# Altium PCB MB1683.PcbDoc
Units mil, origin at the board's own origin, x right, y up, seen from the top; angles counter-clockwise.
Board outline 1732.28 x 2362.2 mil, 4 copper layers (Top Layer, GND, VCC, Bottom Layer), stack 61.59 mil thick; 37 components, 35 nets, 197 pads, 130 vias.
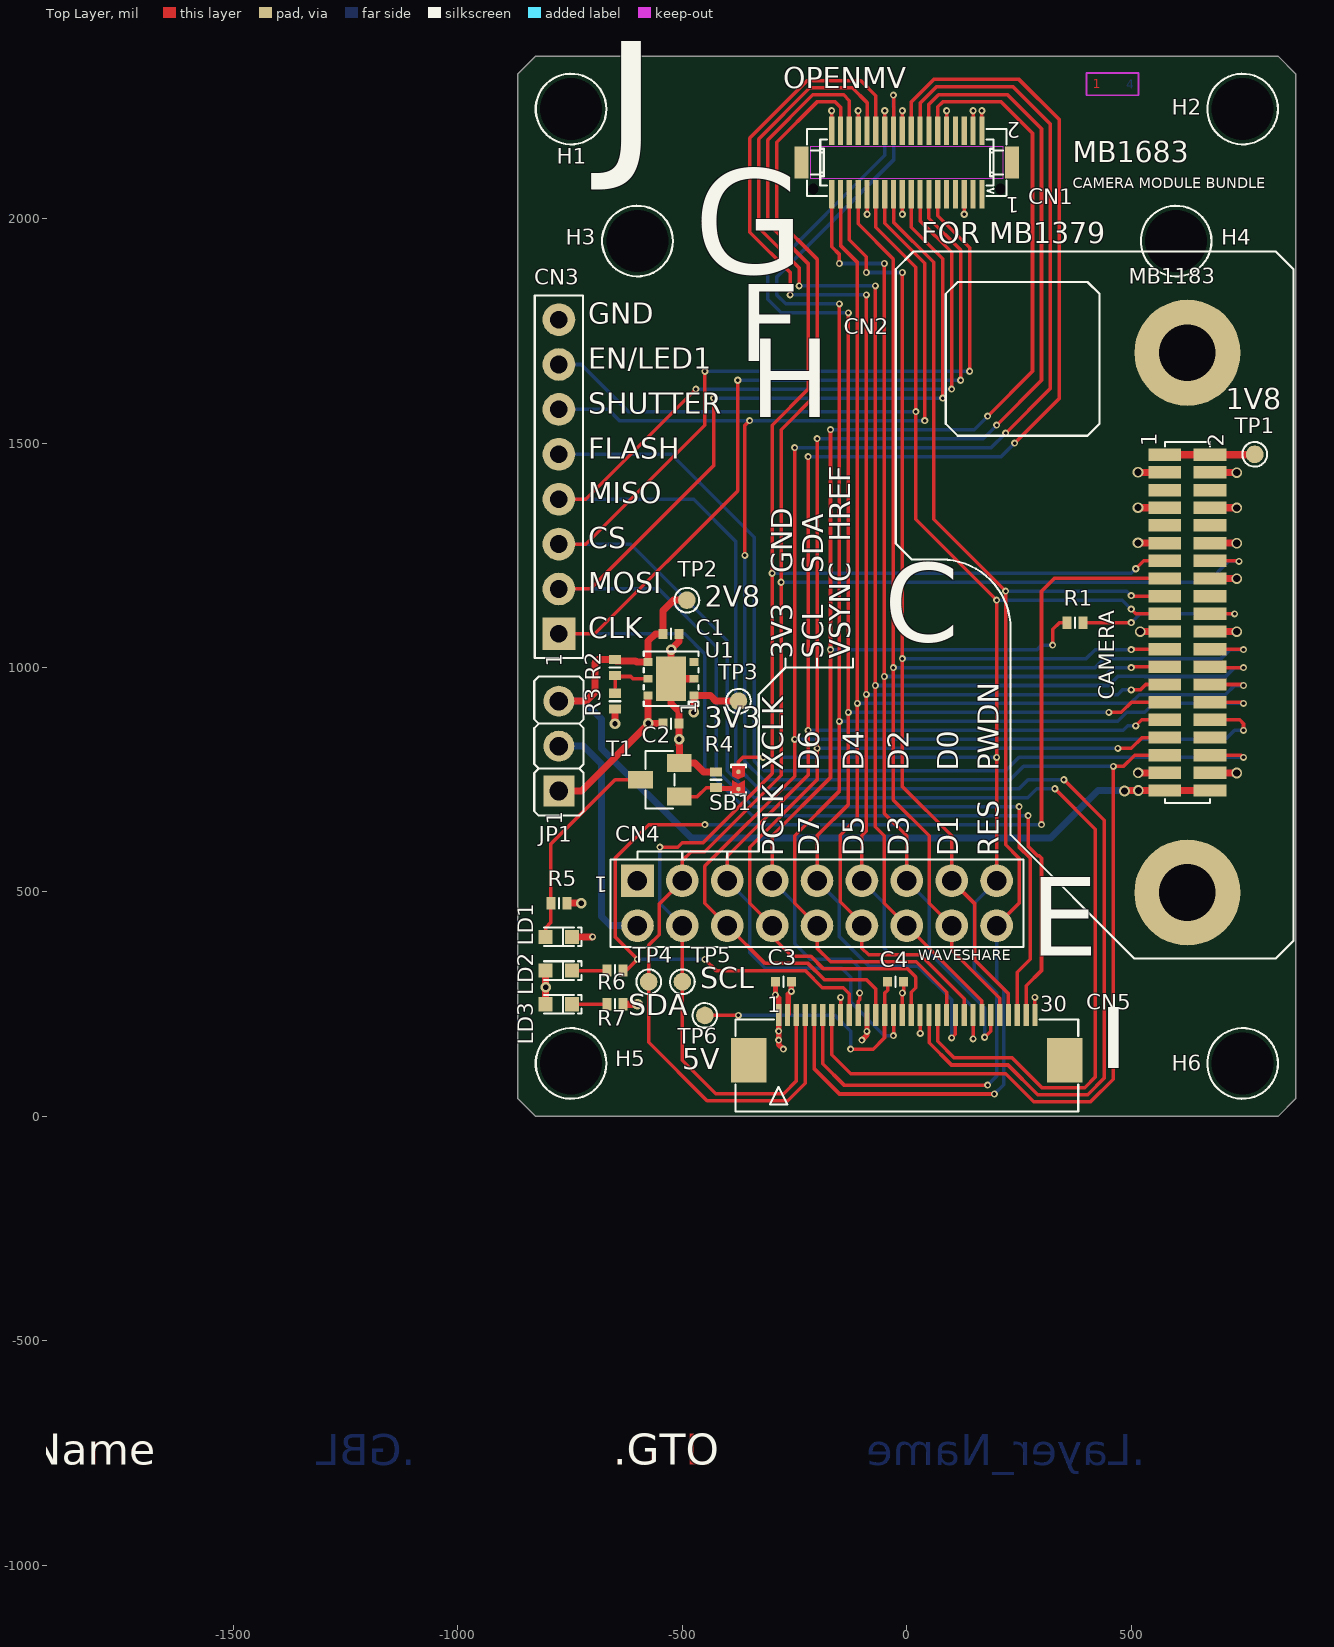
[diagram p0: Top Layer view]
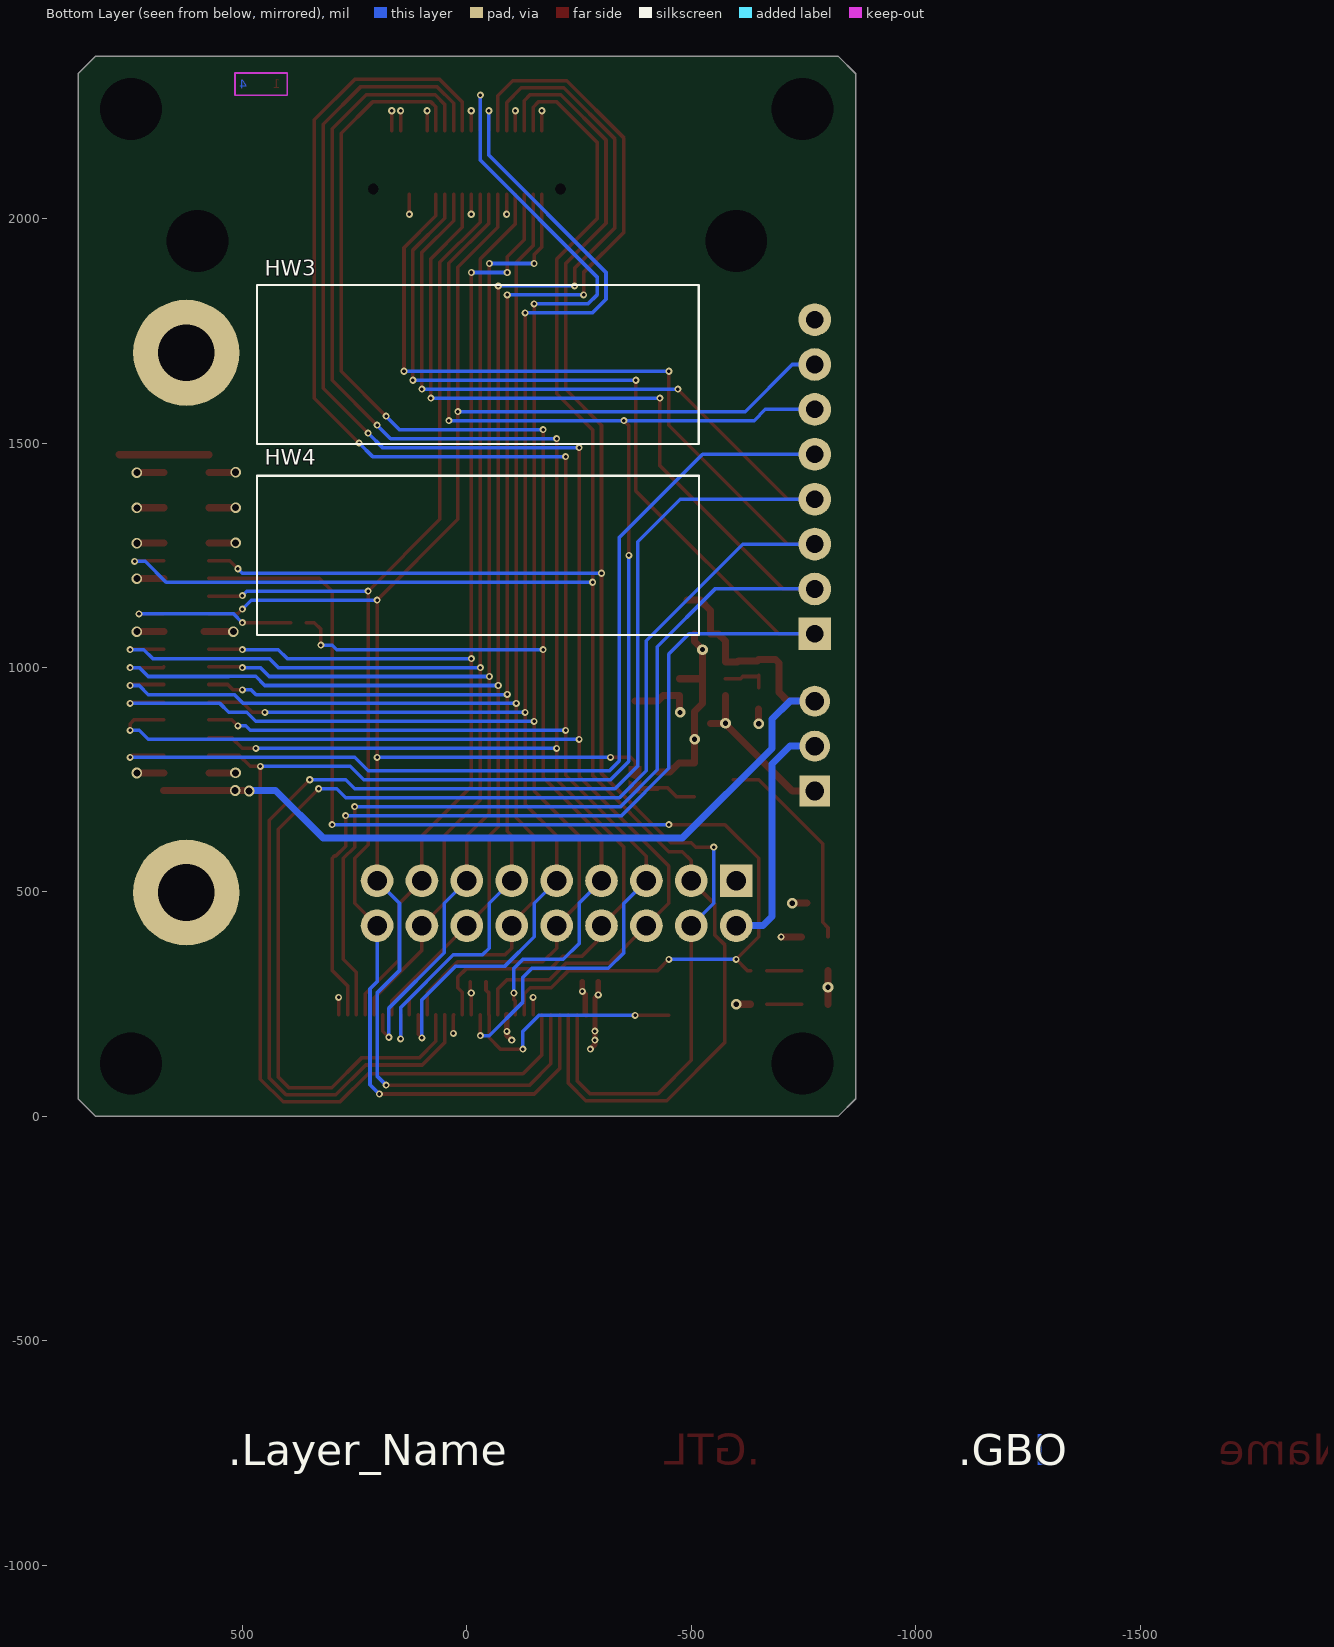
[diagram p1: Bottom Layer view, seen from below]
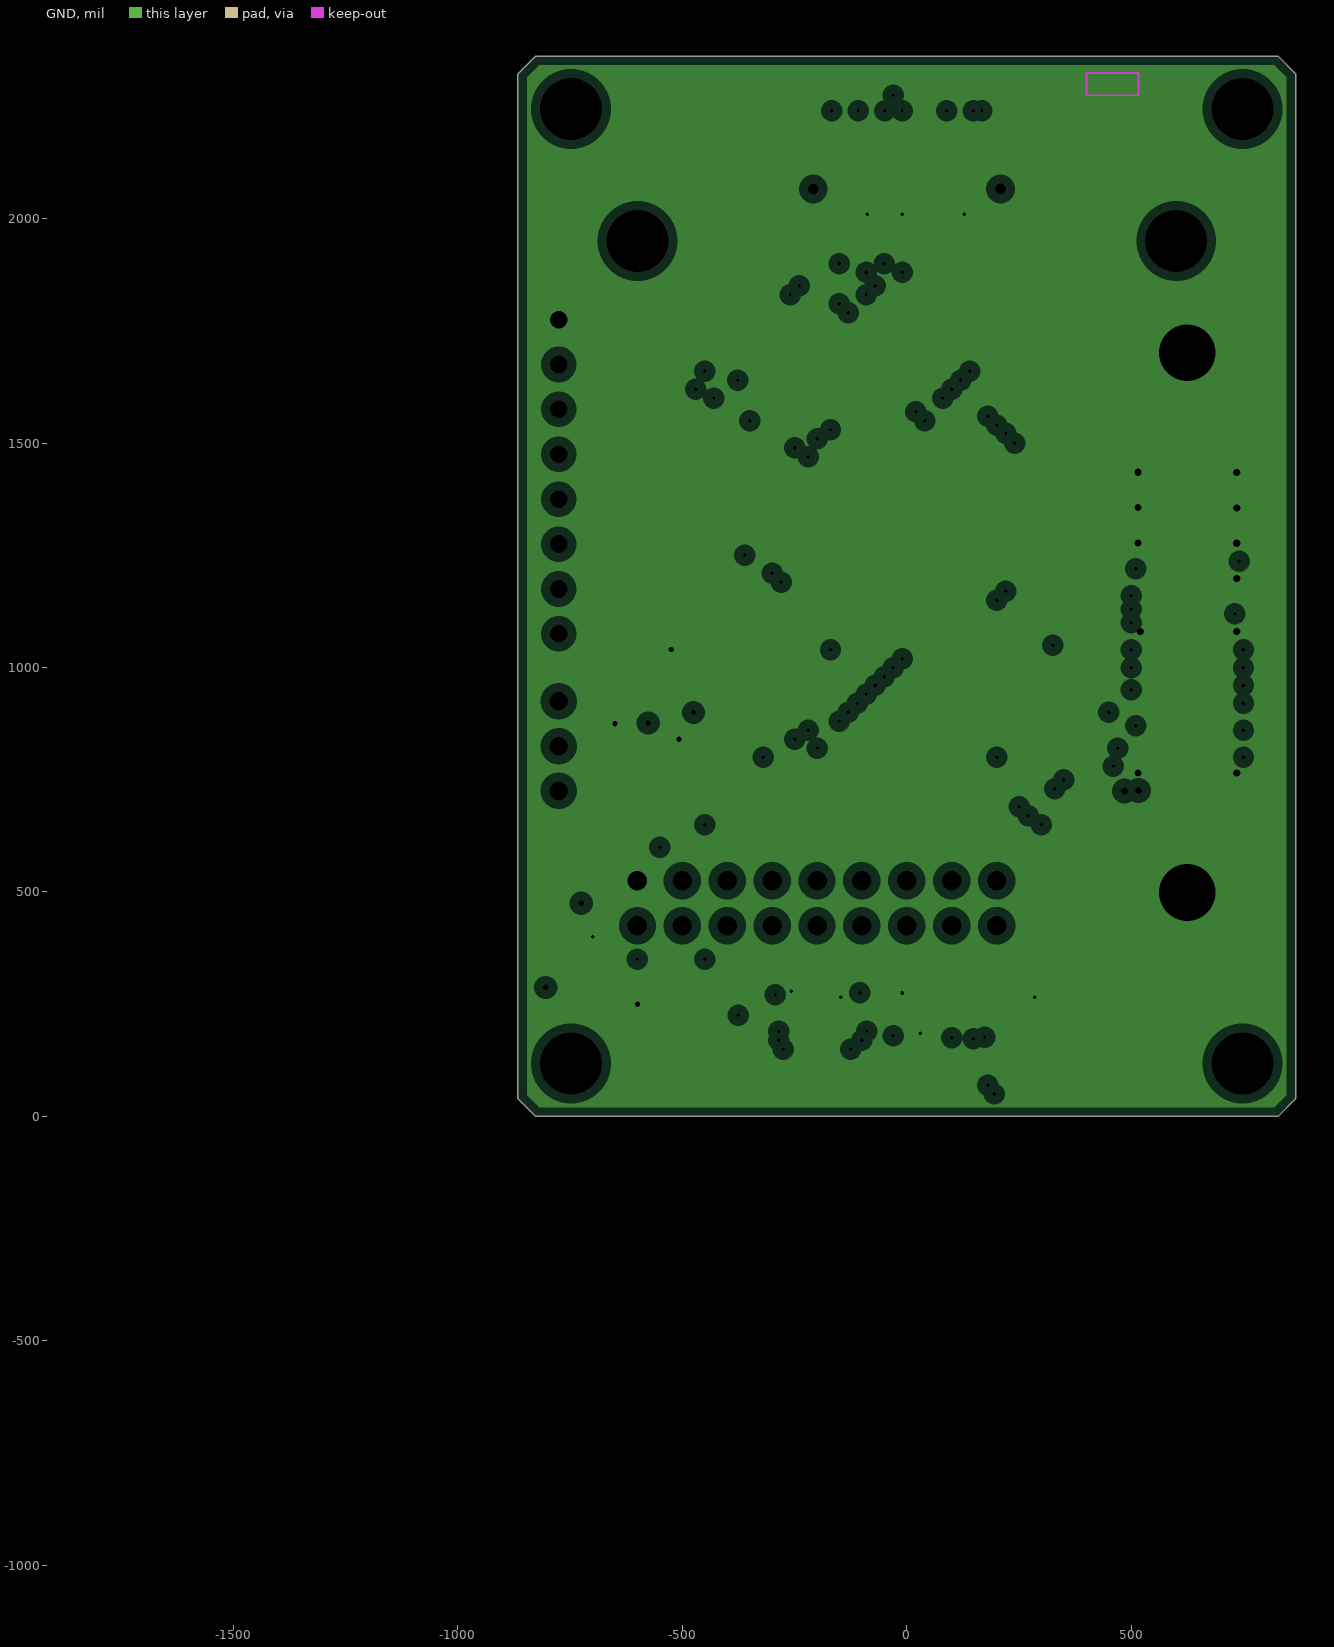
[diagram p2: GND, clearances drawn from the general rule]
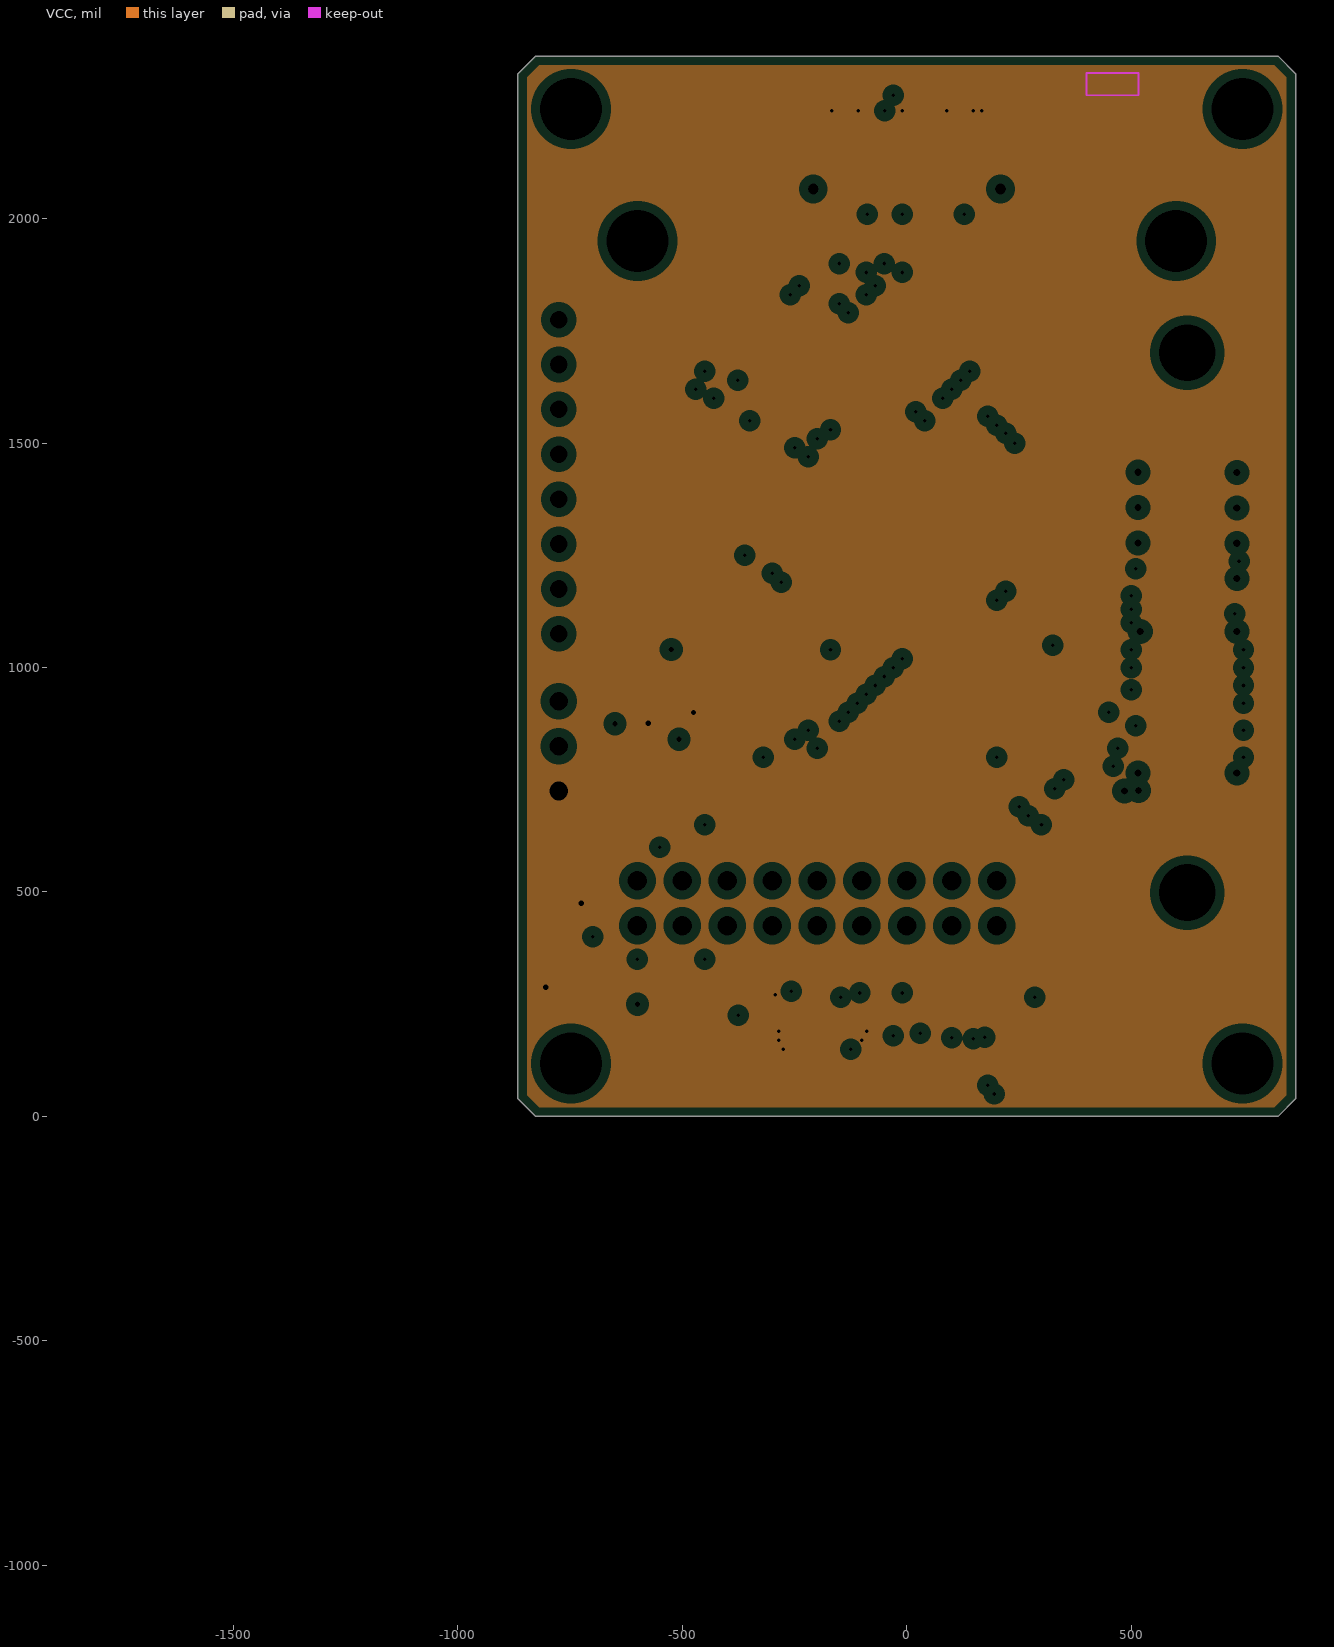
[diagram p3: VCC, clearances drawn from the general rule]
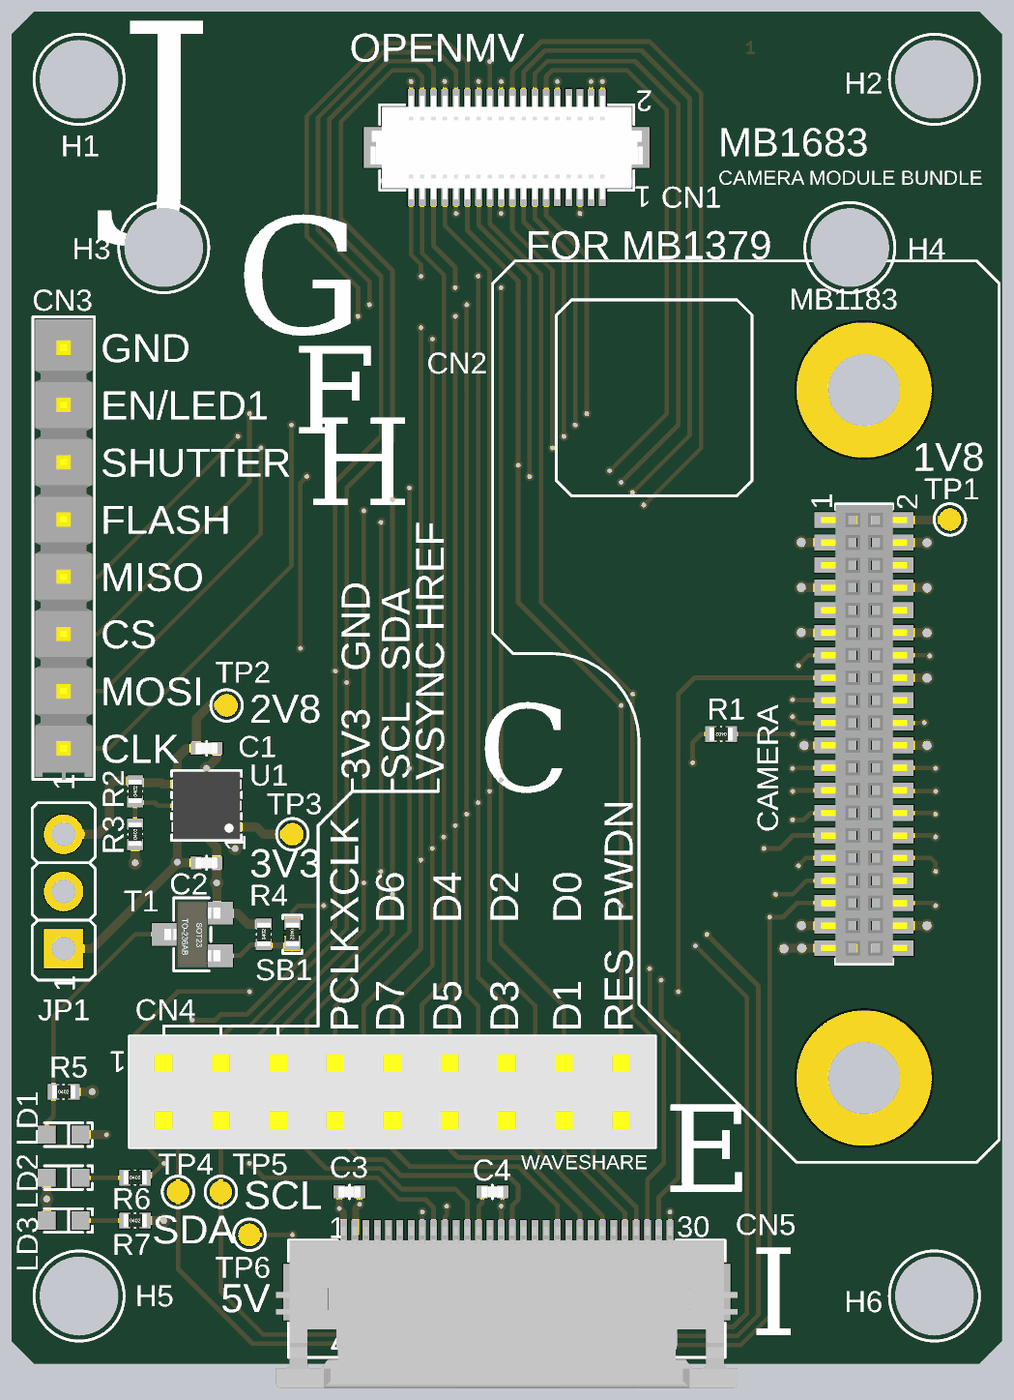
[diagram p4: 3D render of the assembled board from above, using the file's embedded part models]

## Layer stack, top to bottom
Top Solder: solder mask 0.591, Solder Resist, Dk 3.5
Top Layer: signal copper 1.378
Dielectric 1: core 20, FR-4, Dk 4.2
GND: plane copper 1.417, net GND
Dielectric 3: prepreg 16, Dk 4.2
VCC: plane copper 1.417, net 3V3
Dielectric 2: core 20, Dk 4.2
Bottom Layer: signal copper 1.378
Bottom Solder: solder mask 0.591, Solder Resist, Dk 3.5

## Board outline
-866.14,39.37 -866.14,2322.83 -826.77,2362.2 826.77,2362.2 866.14,2322.83 866.14,39.37 826.77,0 -826.77,0

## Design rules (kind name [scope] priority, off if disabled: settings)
Clearance Clearance_CN3 [HasFootprint('CON_HRS_DF12-36DS-0.5V_86')] p1: gap=3.94 ignorepadtopadclearanceinfootprint=FALSE
Clearance Clearance_CN1 [HasFootprint('CON_TOWNES_FPU330ZH-BT1D3-CA_P050')] p2: gap=5.91 ignorepadtopadclearanceinfootprint=FALSE
Clearance [All] p3: gap=7.87 ignorepadtopadclearanceinfootprint=FALSE except(0: Arc-Hole Track-Hole SMDPad-Hole THPad-Hole Via-Hole Fill-Hole Poly-Hole Region-Hole Text-Hole)
ComponentClearance [All] p1: gap=7.87 collisioncheckmode=3 verticalgap=7.87 showdistances=FALSE
HoleSize [All] p1: absolutevalues=TRUE maxlimit=393.7 minlimit=1 maxpercent=80.000 minpercent=20.000
MinimumSolderMaskSliver [All] p1: minsoldermaskwidth=3.15
PlaneClearance [All] p1: clearance=20
PlaneConnect [All] p1: planeconnectstyle=Relief reliefexpansion=20 reliefentries=4 reliefconductorwidth=8.27 reliefairgap=8.27
PolygonConnect PolygonConnect_via [IsVia] p1: connectstyle=Direct reliefconductorwidth=10 reliefentries=4 polygonreliefangle="90 Angle" airgapwidth=10
PolygonConnect [All] p2: connectstyle=Relief reliefconductorwidth=7.87 reliefentries=4 polygonreliefangle="90 Angle" airgapwidth=7.87
RoutingVias [All] p1: holewidth=7.87 width=15.75 viastyle="Through Hole" minholewidth=7.87 minwidth=15.75 maxholewidth=15.75 maxwidth=31.5
SilkToSilkClearance [All] p1: silktosilkclearance=7.87
SilkToSolderMaskClearance [IsPad] p1: minsilkscreentomaskgap=7.87 clearancetoexposedcopper=TRUE
SolderMaskExpansion [All] p1: expansion=4
Width [All] p1: maxlimit=39.37 minlimit=7.87 preferedwidth=7.87 minimp=50.000000 maximp=50.000000 favimp=50.000000
23 further rules are at their usual default settings.

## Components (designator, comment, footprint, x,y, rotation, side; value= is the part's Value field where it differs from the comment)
C1 "Capacitor" C0402 -525,1075 r180 top value=1uF (schematic designator C5)
C2 "Capacitor" C0402 -525,875 r180 top value=1uF (schematic designator C6)
C3 "Capacitor" C0402 -275,300 r180 top value=1uF (schematic designator C7)
C4 "Capacitor" C0402 -25,300 r180 top value=1uF (schematic designator C8)
CN1 "DF12-36DS-0.5V" CON_HRS_DF12-36DS-0.5V_86 0,2125 r180 top locked value=DF12-36DS-0.5V(86) (schematic designator CN3)
CN2 "Socket 20x2 CLM_Reverse_for_camera" CON_SAMTEC_CLM-120-02-L-D_Reverse-to-Camera 625,1100 r0 top locked value=CLM-120-02-L-D
CN3 "Header 8x1" CON_SAMTEC_TSW-108-07-X-S -775,1425 r90 top (schematic designator CN5)
CN4 "Socket 9x2" CON_SAMTEC_SSW-109-01-X-D -200,475 r180 top locked
CN5 "FPU330ZH-BT1D3-CA" CON_TOWNES_FPU330ZH-BT1D3-CA_P050 0,125 r0 top locked (schematic designator CN1)
H1 "POSITION HOLE" NPTH_350 -748.03,2244.09 r0 top (schematic designator H3)
H2 "POSITION HOLE" NPTH_350 748.03,2244.09 r0 top (schematic designator H4)
H3 "POSITION HOLE" NPTH_350 -600,1950 r0 top locked (schematic designator H5)
H4 "POSITION HOLE" NPTH_350 600,1950 r0 top locked (schematic designator H6)
H5 "POSITION HOLE" NPTH_350 -748.03,118.11 r0 top (schematic designator H1)
H6 "POSITION HOLE" NPTH_350 748.03,118.11 r0 top (schematic designator H2)
HW3 "STICKER_BOARD_REF" STICKER_25X9 -24.61,1675 r180 bottom value="MBxxxxy-zz syywwxxxxx"
HW4 "STICKER_BOARD_CPN" STICKER_25X9 -25,1250 r180 bottom value="Board CPN"
JP1 "Jumper_Header 3x1 Fitted 1-2" CON_988-JIUBABA_313103S111116 -775,825 r90 top value="Shunt Fitted 1-2"
LD1 "LED_orange" LED_0603_OSRAM_LO-Q976-PS-25_ORANGE_1A2K_H0P8 -775,400 r0 top value=ORANGE
LD2 "LED_blue" LED_0603_VISHAY_VLMB1300-GS08_BLUE_1A2K_H0P8 -775,325 r0 top value=BLUE
LD3 "LED_green" LED_0603_VISHAY_VLMTG1300-GS08_GREEN_1A2K_H0P8 -775,250 r0 top value=GREEN
R1 "Resistor" R0402 375,1100 r180 top value=0R (schematic designator R7)
R2 "Resistor" R0402 -650,1000 r90 top value=24K9
R3 "Resistor" R0402 -650,925 r90 top value="10K - 0.5%" (schematic designator R4)
R4 "Resistor" R0402 -425,750 r90 top value=1M (schematic designator R3)
R5 "Resistor" R0402 -775,475 r0 top value=360R (schematic designator R1)
R6 "Resistor" R0402 -650,325 r0 top value=270R (schematic designator R5)
R7 "Resistor" R0402 -650,250 r0 top value=270R (schematic designator R6)
SB1 "SB_ON" SOLDER-BRIDGE_R0402-0R -375,750 r270 top
T1 "BSN20" MOS_SOT23 -550,750 r90 top value=BSN20BK
TP1 "Test Point" TP_SMD_1MM 775,1475 r90 top (schematic designator TP4)
TP2 "Test Point" TP_SMD_1MM -490,1150 r90 top (schematic designator TP15)
TP3 "Test Point" TP_SMD_1MM -375,925 r90 top (schematic designator TP2)
TP4 "Test Point" TP_SMD_1MM -575,300 r90 top (schematic designator TP3)
TP5 "Test Point" TP_SMD_1MM -500,300 r0 top (schematic designator TP1)
TP6 "Test Point" TP_SMD_1MM -450,225 r90 top (schematic designator TP5)
U1 "LD39050PUR" ICC_DFN6-EPAD_3X3_P095 -525,975 r90 top

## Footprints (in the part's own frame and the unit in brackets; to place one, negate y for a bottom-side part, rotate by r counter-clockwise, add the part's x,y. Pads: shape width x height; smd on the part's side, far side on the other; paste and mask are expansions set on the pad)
C0402 [mm]
  rect 0.51x0.56 smd mask+0.05: 1(-0.45,0) 2(0.45,0)
  silkscreen extent 0,-0.3 0,0.3, body extent -0.5,-0.3 0.5,0.3, height 0.4
CON_988-JIUBABA_313103S111116 [mm] "MCD-01656"
  rect 1.75x1.75 hole 1.05 mask+0.05: 1(-2.54,0)
  round 1.75 hole 1.05 mask+0.05: 2(0,0) 3(2.54,0)
  silkscreen extent -3.94,-1.4 3.94,1.4, body extent -3.94,-1.4 3.94,1.4, height 8.94
CON_HRS_DF12-36DS-0.5V_86 [mm] "MCD-02158"
  round 0 hole 0.6 unplated mask+0.05: 0(-5.3,1.5) 0(5.3,1.5)
  rect 0.3x1.6 smd mask+0.05: 1(-4.25,1.8) 2(-4.25,-1.8) 3(-3.75,1.8) 4(-3.75,-1.8) 5(-3.25,1.8) 6(-3.25,-1.8) 7(-2.75,1.8) 8(-2.75,-1.8) 9(-2.25,1.8) 10(-2.25,-1.8) 11(-1.75,1.8) 12(-1.75,-1.8) 13(-1.25,1.8) 14(-1.25,-1.8) 15(-0.75,1.8) 16(-0.75,-1.8) 17(-0.25,1.8) 18(-0.25,-1.8) 19(0.25,1.8) 20(0.25,-1.8) 21(0.75,1.8) 22(0.75,-1.8) 23(1.25,1.8) 24(1.25,-1.8) 25(1.75,1.8) 26(1.75,-1.8) 27(2.25,1.8) 28(2.25,-1.8) 29(2.75,1.8) 30(2.75,-1.8) 31(3.25,1.8) 32(3.25,-1.8) 33(3.75,1.8) 34(3.75,-1.8) 35(4.25,1.8) 36(4.25,-1.8)
  rect 0.8x1.8 smd mask+0.05: 37(-5.95,0) 38(5.95,0)
  Top Layer keep-out region: -5.45,0.9 -5.45,-0.9 5.45,-0.9 5.45,0.9
  silkscreen extent -5.65,-1.9 5.65,1.9, body extent -6.05,-2.3 6.05,2.3, height 2.9
CON_SAMTEC_CLM-120-02-L-D_Reverse-to-Camera [mm] "not in line with Samtec spec"
  rect 1.85x0.7 smd mask+0.05: 1(-1.275,9.5) 2(1.275,9.5) 3(-1.275,8.5) 4(1.275,8.5) 5(-1.275,7.5) 6(1.275,7.5) 7(-1.275,6.5) 8(1.275,6.5) 9(-1.275,5.5) 10(1.275,5.5) 11(-1.275,4.5) 12(1.275,4.5) 13(-1.275,3.5) 14(1.275,3.5) 15(-1.275,2.5) 16(1.275,2.5) 17(-1.275,1.5) 18(1.275,1.5) 19(-1.275,0.5) 20(1.275,0.5) 21(-1.275,-0.5) 22(1.275,-0.5) 23(-1.275,-1.5) 24(1.275,-1.5) 25(-1.275,-2.5) 26(1.275,-2.5) 27(-1.275,-3.5) 28(1.275,-3.5) 29(-1.275,-4.5) 30(1.275,-4.5) 31(-1.275,-5.5) 32(1.275,-5.5) 33(-1.275,-6.5) 34(1.275,-6.5) 35(-1.275,-7.5) 36(1.275,-7.5) 37(-1.275,-8.5) 38(1.275,-8.5) 39(-1.275,-9.5) 40(1.275,-9.5)
  round 6 hole 3.2 mask+0.1: 41(0,15.27) 42(0,-15.27)
  silkscreen extent -16.5,-19 6,21, body extent -16.5,-19 6,21, height 5.69
CON_SAMTEC_SSW-109-01-X-D [mm] "MCD-02157"
  rect 1.85x1.85 / inner round 1.85 / far side rect 1.85x1.85 hole 1.1 mask+0.05: 1(10.16,-1.27)
  round 1.85 hole 1.1 mask+0.05: 2(10.16,1.27) 3(7.62,-1.27) 4(7.62,1.27) 5(5.08,-1.27) 6(5.08,1.27) 7(2.54,-1.27) 8(2.54,1.27) 9(0,-1.27) 10(0,1.27) 11(-2.54,-1.27) 12(-2.54,1.27) 13(-5.08,-1.27) 14(-5.08,1.27) 15(-7.62,-1.27) 16(-7.62,1.27) 17(-10.16,-1.27) 18(-10.16,1.27)
  silkscreen extent -11.69,-2.47 11.69,2.47, body extent -11.68,-2.48 11.69,2.48, height 8.51
CON_SAMTEC_TSW-108-07-X-S [mm]
  rect 1.85x1.85 / inner round 1.85 / far side rect 1.85x1.85 hole 1 mask+0.05: 1(-8.89,0)
  round 1.85 hole 1 mask+0.05: 2(-6.35,0) 3(-3.81,0) 4(-1.27,0) 5(1.27,0) 6(3.81,0) 7(6.35,0) 8(8.89,0)
  silkscreen extent -10.27,-1.37 10.26,1.37, body extent -10.29,-1.37 10.26,1.37, height 8.38
CON_TOWNES_FPU330ZH-BT1D3-CA_P050 [mm]
  rect 0.3x1.25 smd mask+0.05: 1(-7.25,2.575) 2(-6.75,2.575) 3(-6.25,2.575) 4(-5.75,2.575) 5(-5.25,2.575) 6(-4.75,2.575) 7(-4.25,2.575) 8(-3.75,2.575) 9(-3.25,2.575) 10(-2.75,2.575) 11(-2.25,2.575) 12(-1.75,2.575) 13(-1.25,2.575) 14(-0.75,2.575) 15(-0.25,2.575) 16(0.25,2.575) 17(0.75,2.575) 18(1.25,2.575) 19(1.75,2.575) 20(2.25,2.575) 21(2.75,2.575) 22(3.25,2.575) 23(3.75,2.575) 24(4.25,2.575) 25(4.75,2.575) 26(5.25,2.575) 27(5.75,2.575) 28(6.25,2.575) 29(6.75,2.575) 30(7.25,2.575)
  rect 2x2.5 smd mask+0.05: 31(-8.94,0) 32(8.94,0)
  silkscreen extent -9.7,-2.9 9.7,2.3, body extent -10.25,-4.25 10.25,3, height 2.05
ICC_DFN6-EPAD_3X3_P095 [mm]
  rect 0.45x0.5 smd mask+0.05: 1(-0.95,-1.3) 2(0,-1.3) 3(0.95,-1.3) 4(0.95,1.3) 5(0,1.3) 6(-0.95,1.3)
  rect 2.5x1.7 smd mask+0.05: EP(0,0)
  silkscreen extent -1.55,-1.55 1.55,1.55, body extent -1.55,-1.55 1.55,1.55, height 1
LED_0603_OSRAM_LO-Q976-PS-25_ORANGE_1A2K_H0P8 [mm]
  rect 0.8x0.8 smd mask+0.05: 1(-0.75,0) 2(0.75,0)
  silkscreen extent -0.85,-0.53 1.28,0.53, body extent -0.85,-0.45 0.85,0.45, height 0.8
LED_0603_VISHAY_VLMB1300-GS08_BLUE_1A2K_H0P8 [mm]
  rect 0.8x0.8 smd mask+0.05: 1(-0.75,0) 2(0.75,0)
  silkscreen extent -0.85,-0.53 1.28,0.53, body extent -0.85,-0.45 0.85,0.45, height 0.8
LED_0603_VISHAY_VLMTG1300-GS08_GREEN_1A2K_H0P8 [mm]
  rect 0.8x0.8 smd mask+0.05: 1(-0.75,0) 2(0.75,0)
  silkscreen extent -0.85,-0.53 1.28,0.53, body extent -0.85,-0.45 0.85,0.45, height 0.8
MOS_SOT23 [mm]
  rect 1x1.4 smd mask+0.05: 1(-0.95,-1.1) 2(0.95,-1.1) 3(0,1.1)
  silkscreen extent -1.63,-0.82 1.63,0.82, body extent -1.56,-1.25 1.56,1.25, height 1.1
NPTH_350 [mm]
  round 0 hole 3.5 unplated mask+0.05: 1(0,0)
  silkscreen extent -2,-2 2,2
R0402 [mm]
  rect 0.51x0.7 smd mask+0.05: 1(-0.45,0) 2(0.45,0)
  silkscreen extent 0,-0.3 0,0.3, body extent -0.52,-0.3 0.52,0.3, height 0.4
SOLDER-BRIDGE_R0402-0R [mil] "MCD-01619"
  round 10 smd paste-393.7: 1(-17.72,0) 2(20.67,0)
  Top Layer region: 1.48,13.78 8.37,0 1.48,-13.78 30.51,-13.78 30.51,13.78
  Top Layer region: -30.51,-13.78 -30.51,13.78 -8.37,13.78 -1.48,0 -8.37,-13.78
  silkscreen extent -33,-17 33,17, body extent -20,-12 20,12, height 14
STICKER_25X9 [mil] "Sticker 25mm x 9mm"
  silkscreen extent -492,-177 492,177
TP_SMD_1MM [mm]
  round 1 smd paste-10 mask+0.05: 1(0,0)
  silkscreen extent -0.7,-0.7 0.7,0.7

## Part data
C1 C2 C3 C4: library part MCD-00010, "Capacitor, MLCC, 1uF, 16V, X5R, +/-10%, 0603, T=0,8mm", Alternate_Manufacturer=MURATA, Alternate_Manufacturer_Part_Number=GCM155R71C104KA55D, Manufacturer=YAGEO, Manufacturer_Part_Number=CC0603KRX5R7BB105, Package=C0603
CN1: library part MCD-02158, "Receptacle, 18x2, 0.5mm, Straight,SMT, height 2.7mm", Alternate_Manufacturer=N/A, Manufacturer=HIROSE, Manufacturer_Part_Number=DF12-36DS-0.5V(86)
CN2: library part MCD-00138, "Socket, 20x2, 1.0mm, VR, SMT, Height 2.26mm. Symbol & Footprint dedicated to MB1183 & MB1379 camera modules (not in line with Samtec datasheet)", Manufacturer=SAMTEC, Manufacturer_Part_Number=CLM-120-02-L-D
CN3: library part MCD-00239, "Header, 8x1, 2,54mm, VR, TH, Height 5.84mm/2.54mm", Manufacturer=SAMTEC, Manufacturer_Part_Number=TSW-108-07-G-S
CN4: library part MCD-02157, "Socket, 9x2, 2.54mm, VR, TH, Height 8.51mm/2.64mm, Standard insertion force.", Alternate_Manufacturer=N/A, Manufacturer=SAMTEC, Manufacturer_Part_Number=SSW-109-01-G-D
CN5: library part MCD-00326, "Connector FFC/FPC ZIF 0.5mm 30 pins, Lower Contacts", Manufacturer=TOWNES
H1 H2 H3 H4 H5 H6: library part MCD-01368, "POSITION HOLE C3R5D3R5", Manufacturer=N/A
HW3: library part MCD-00235, "Sticker to mention board reference + serial number", Manufacturer=N/A, Manufacturer_Part_Number=n/a
HW4: library part MCD-00547, "Sticker to mention board CPN code", Manufacturer=N/A, Manufacturer_Part_Number=n/a
JP1: library part MCD-01656, "Header 3x1, 2.54mm, VR, TH, height 6 mm / 3 mm, total 11.6mm - Shunt Fitted 1-2 by default", Manufacturer=JIUBABA, Manufacturer_Part_Number=313103S111116
LD1: library part MCD-00590, "LED Orange, 0603 SMD, Forward Voltage Min=1.6V, Max=2.4V", Alternate_Manufacturer="VISHAY SEMICONDUCTOR OPTO DIVISION", Alternate_Manufacturer_Part_Number=VLMO1300-GS08, Manufacturer="OSRAM OPTO SEMICONDUCTORS", Manufacturer_Part_Number="LO Q976-PS-25", Package="LED 0603"
LD2: library part MCD-00585, "LED Blue, 0603 SMD, Forward Voltage Min=2,8V, Max=3,8V", Alternate_Manufacturer=EVERLIGHT, Alternate_Manufacturer_Part_Number=19-217-BHC-ZL1M2RY-3T-V4, Manufacturer="OSRAM OPTO SEMICONDUCTORS", Manufacturer_Part_Number="LB Q39G-L2OO-35-1", Package="LED 0603"
LD3: library part MCD-00588, "LED Green, 0603 SMD, Forward Voltage Typ=2V, Max=2.5V", Alternate_Manufacturer="VISHAY SEMICONDUCTOR OPTO DIVISION", Alternate_Manufacturer_Part_Number=VLMTG1300-GS08, Manufacturer="OSRAM OPTO SEMICONDUCTORS", Manufacturer_Part_Number="LG Q396-PS-35", Package="LED 0603"
R1: library part MCD-00056, "Resistor,0R,0603,5%,1/10W", Alternate_Manufacturer=YAGEO, Alternate_Manufacturer_Part_Number=RT0402FRE07100KL, Manufacturer_Part_Number=RC0603JR-070RL, Package=R0603
R2: library part MCD-01170, "Resistor,24K9,0603,1%,1/10W", Alternate_Manufacturer=YAGEO, Alternate_Manufacturer_Part_Number=RT0402FRE07100KL, Manufacturer_Part_Number=RC0603FR-0724K9L, Package=R0603
R3: library part MCD-01215, "Resistor, 10K, 0603, 0.5%, 1/10W,±100ppm/°C", Alternate_Manufacturer=YAGEO, Alternate_Manufacturer_Part_Number=RT0402FRE07100KL, Manufacturer_Part_Number=RC0603DR-0710KL, Package=R0603
R4: library part MCD-00257, "Resistor,1M,0603,1%,1/10W", Alternate_Manufacturer=YAGEO, Alternate_Manufacturer_Part_Number=RT0402FRE07100KL, Manufacturer_Part_Number=RC0603FR-071ML, Package=R0603
R5: library part MCD-00462, "Resistor,360R,0603,1%,1/10W", Alternate_Manufacturer=YAGEO, Alternate_Manufacturer_Part_Number=RT0402FRE07100KL, Manufacturer_Part_Number=RC0603FR-07360RL, Package=R0603
R6 R7: library part MCD-00442, "Resistor,270R,0603,1%,1/10W", Alternate_Manufacturer=YAGEO, Alternate_Manufacturer_Part_Number=RT0402FRE07100KL, Manufacturer_Part_Number=RC0603FR-07270RL, Package=R0603
SB1: library part MCD-00071, "Solder Bridge ON", Manufacturer=YAGEO, Manufacturer_Part_Number=RC0603JR-070RL, Package=SB0603
T1: library part MCD-01969, "Transistor, N-channel enhancement mode field-effect transistor", Alternate_Manufacturer=N/A, Manufacturer=NEXPERIA, Manufacturer_Part_Number=BSN20BK
TP1 TP2 TP3 TP4 TP5 TP6: library part MCD-00074, "Test Point 1mm", Manufacturer=N/A, Manufacturer_Part_Number=n/a
U1: library part MCD-02161, "Low quiescent current and low noise voltage regulators", Alternate_Manufacturer=N/A, Manufacturer=STMICROELECTRONICS, Package="DFN6 3x3mm"

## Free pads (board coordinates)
  round 20 on Mech16: 1(-1836.22,-1049.31) 1(86.9,-1049.31)

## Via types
v1: diameter 15.75, hole 7.87, Top Layer to Bottom Layer, tented both sides, 109 vias
v2: diameter 23.62, hole 15.75, Top Layer to Bottom Layer, tented both sides, 13 vias
v3: diameter 23.62, hole 11.81, Top Layer to Bottom Layer, tented both sides, 8 vias

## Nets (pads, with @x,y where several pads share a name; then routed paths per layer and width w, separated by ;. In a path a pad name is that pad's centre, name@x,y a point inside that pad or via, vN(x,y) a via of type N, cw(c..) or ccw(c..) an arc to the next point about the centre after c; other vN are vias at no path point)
1V8: CN2.1 CN2.2 TP1.1 | length 200.6
  Top Layer w15.75: CN2.1 CN2.2 774.02,1474.02 TP1.1
2V8: C1.2 CN2.39 CN2.40 JP1.3 R2.2 TP2.1 U1.4 | length 2137.4
  Top Layer w15.75: JP1.3 -715,925 -695,945 -695,1010 -687.28,1017.72 R2.2 -647.28,1015 -605,1015 -602.4,1012.4 U1.4 -576.18,1058.82 -560,1075 C1.2 -542.72,1127.28 -520,1150 TP2.1 ; v2(485,725) 485.98,725.98 v2(515.98,725.98) CN2.39 CN2.40
  Bottom Layer w15.75: JP1.3 -720,925 -680,885 -680,820 -480,620 320,620 425.98,725.98 v2@485,725.98
3V3: C2.2 C3.2 CN1.2 CN1.4 CN1.10 CN1.20 CN1.30 CN1.36 CN5.1 CN5.11 JP1.1 LD2.1 LD3.1 R5.2 TP3.1 U1.1 U1.6 | length 1067.6
  Top Layer w7.87: CN1.36 v1@-167.32,2235.43 ; CN1.30 v1@-108.27,2235.43 ; CN1.20 v1@-9.84,2235.43 ; CN1.10 88.58,2235.43 v1(88.58,2240.24) ; CN1.4 v1@147.64,2235.43 ; CN1.2 v1@167.32,2235.43
  Top Layer w11.81: C3.2 v1(-292.72,270.88) -285.44,263.6 CN5.1 -285.44,160.44 v1(-275,150) ; v1(-100,170) -88.59,181.41 CN5.11
  Top Layer w15.75: LD3.1 v3(-804.53,287.5) LD2.1 ; JP1.1 -725,725 v3@-575,875 ; R5.2 v3(-725,475) ; U1.6 v3(-576.18,876.18) v3@-575,875 ; C2.2 v3@-575,875 ; v3(-475,900) -473.82,901.18 U1.1 -437.6,937.6 -425,925 TP3.1
  other v1: -285.44,170 -285.44,190 -89.06,189.53 -167.32,2240.24 -108.27,2240.24 -9.84,2240.24 147.64,2240.24 167.32,2240.24
5V: C4.2 CN5.13 TP6.1 | length 592.9
  Top Layer w7.87: TP6.1 v1(-375,225) ; v1(-125,150) -75,150 -49.68,175.31 -49.68,225.91 CN5.13 -49.22,275 -42.72,281.5 C4.2
  Bottom Layer w7.87: v1(-375,225) -160,225 -125,190 v1(-125,150)
Camera_CLK: CN1.12 CN4.7 CN5.10 R1.2 | length 3396.5
  Top Layer w7.87: CN4.7 -300,625 -170,755 v1(-170,1040) v1(-170,1530) ; CN5.10 -108.27,256.73 -105,260 v1(-105,275) ; CN1.12 68.9,2248.9 79.92,2259.92 210.08,2259.92 280,2190 280,1660 v1(180,1560) ; v1(325,1050) 325,1085 340,1100 R1.2
  Bottom Layer w7.87: CN4.7 -250,475 -250,385 -215,350 -125,350 -105,330 v1(-105,275) ; v1(-170,1040) 290,1040 300,1050 v1(325,1050) ; v1(-170,1530) 150,1530 v1(180,1560)
DCMI_D0: CN1.31 CN2.23 CN4.15 CN5.27 | length 2614.9
  Top Layer w7.87: CN1.31 -127.95,1952.95 -90,1915 v1(-90,1880) ; v1(-10,1880) v1(-10,1020) -10,735 100,625 CN4.15 151.77,473.23 151.77,348.23 226.37,273.63 CN5.27 ; v1(500,1040) 500.94,1040.94 CN2.23
  Bottom Layer w7.87: v1(-90,1880) v1(-10,1880) ; v1(-10,1020) 400,1020 420,1040 v1(500,1040)
DCMI_D1: CN1.29 CN2.24 CN4.16 CN5.26 | length 2830
  Top Layer w7.87: CN1.29 -108.27,1988.27 -30,1910 v1(-30,1000) -30,705 50,625 50,475 CN4.16 100,370 206.69,263.31 CN5.26 ; CN2.24 749.06,1040.94 v1(750,1040)
  Bottom Layer w7.87: v1(-30,1000) 420,1000 440,1020 700,1020 720,1040 v1(750,1040)
DCMI_D2: CN1.35 CN2.25 CN4.13 CN5.25 | length 2766.6
  Top Layer w7.87: CN1.35 -167.32,1937.41 -150,1920.09 v1(-150,1900) ; v1(-50,1900) v1(-50,980) -50,675 0,625 CN4.13 ; v1(173.53,176.47) 187,189.95 CN5.25 ; v1(500,1000) 501.57,1001.57 CN2.25
  Bottom Layer w7.87: v1(-150,1900) v1(-50,1900) ; v1(-50,980) 440,980 460,1000 v1(500,1000) ; CN4.13 50,475 50,365 173.53,241.47 v1(173.53,176.47)
DCMI_D3: CN1.28 CN2.26 CN4.14 CN5.24 | length 3539.6
  Top Layer w7.87: v1(-240,1850) -240,1890 -330,1980 -330,2177.27 -215.85,2291.42 -121.42,2291.42 -88.58,2258.58 CN1.28 ; v1(-70,1850) v1(-70,960) -70,645 -50,625 -50,475 CN4.14 10,425 10,415 167.32,257.68 CN5.24 ; CN2.26 676.77,1000 v1(750,1000)
  Bottom Layer w7.87: v1(-240,1850) v1(-70,1850) ; v1(-70,960) 450,960 470.32,980.31 529.68,980.31 530,980 710,980 730,1000 v1(750,1000)
DCMI_D4: CN1.26 CN2.27 CN4.11 CN5.23 | length 3512.9
  Top Layer w7.87: v1(-260,1830) -260,1880 -350,1970 -350,2179.54 -222.38,2307.17 -102.17,2307.17 -68.9,2273.9 CN1.26 ; CN4.11 -100,625 -90,635 v1(-90,940) v1(-90,1830) ; v1(147.63,172.63) CN5.23 ; v1(500,950) 520,950 532.2,962.2 CN2.27
  Bottom Layer w7.87: v1(-260,1830) v1(-90,1830) ; CN4.11 -50,475 -50,375 -35,360 30,360 147.63,242.37 v1(147.63,172.63) ; v1(-90,940) -89.57,939.57 469.57,939.57 480,950 v1(500,950)
DCMI_D5: CN1.33 CN2.28 CN4.12 CN5.22 | length 2993.2
  Top Layer w7.87: CN1.33 -147.64,1940 -110,1902.36 v1(-110,920) -110,665 -148.23,626.77 -148.23,478.23 -100,430 CN4.12 -100,375 -85,360 30,360 127.95,262.05 CN5.22 ; CN2.28 747.8,962.2 v1(750,960)
  Bottom Layer w7.87: v1(-110,920) 497.84,920 517.52,939.69 709.68,939.69 730,960 v1(750,960)
DCMI_D6: CN1.24 CN2.29 CN4.9 CN5.21 | length 3366.8
  Top Layer w7.87: CN4.9 -200,625 -130,695 v1(-130,900) v1(-130,1790) ; CN1.24 v1(-49.21,2240.24) ; v1(100,175) 108.26,183.26 CN5.21 ; v1(450,900) 477.84,900 500.67,922.83 CN2.29
  Bottom Layer w7.87: CN4.9 -150,475 -150,400 -85,335 25,335 100,260 v1(100,175) ; v1(-130,900) v1(450,900) ; v1(-130,1790) -280,1790 -310,1820 -310,1880 -49.21,2140.79 v1(-49.21,2240.24)
DCMI_D7: CN1.22 CN2.30 CN4.10 CN5.20 | length 3654.6
  Top Layer w7.87: v1(-150,1810) v1(-150,880) -150,725 -250,625 -250,475 CN4.10 -200,375 -169.25,344.25 20.75,344.25 88.58,276.42 CN5.20 ; v1(-30,2275) -29.53,2274.53 CN1.22 ; CN2.30 752.17,922.83 750,920.67 v1(750,920)
  Bottom Layer w7.87: v1(-150,880) 470,880 490,900 530,900 550,920 v1(750,920) ; v1(-150,1810) -270,1810 -290,1830 -290,1870 -29.53,2130.47 -29.53,2248.39 -30,2248.86 v1(-30,2275)
DCMI_HSYNC: CN1.18 CN2.31 CN4.5 CN5.14 | length 4166.2
  Top Layer w7.87: CN4.5 -400,580 -220,760 v1(-220,860) v1(-220,1470) ; v1(-30,180) -29.53,180.47 CN5.14 ; CN1.18 9.84,2259.84 60,2310 250,2310 340,2220 340,1600 v1(240,1500) ; v1(510,870) 523.46,883.46 CN2.31
  Bottom Layer w7.87: CN4.5 -350,475 -350,365 -315,330 -145,330 -125,310 -125,255 -50,180 v1(-30,180) ; v1(-220,860) 482.27,860 492.27,870 v1(510,870) ; v1(-220,1470) 210,1470 v1(240,1500)
DCMI_PIXCLK: CN1.14 CN2.33 CN4.8 CN5.16 | length 3886.2
  Top Layer w7.87: v1(-200,1510) v1(-200,820) -200,750 -350,600 -350,475 CN4.8 -300,400 -256.5,356.5 -213.53,356.5 -185.54,328.5 1.98,328.5 20,310.48 20,286.76 9.84,276.6 CN5.16 ; CN1.14 49.21,2254.21 70.67,2275.67 224.33,2275.67 300,2200 300,1640 v1(200,1540) ; v1(470,820) 500,820 524.09,844.09 CN2.33
  Bottom Layer w7.87: v1(-200,820) v1(470,820) ; v1(-200,1510) 170,1510 v1(200,1540)
DCMI_VSYNC: CN1.16 CN2.32 CN4.6 CN5.12 | length 4331.6
  Top Layer w7.87: v1(-250,1490) v1(-250,840) -250,757.73 -450,557.73 -450,475 CN4.6 -315.75,340.75 -220.06,340.75 -184.31,305 -90,305 -68.9,283.9 CN5.12 ; CN1.16 29.53,2256.8 66.98,2294.25 235.75,2294.25 320,2210 320,1622.16 v1(220,1522.16) ; CN2.32 741.54,883.46 750,875 v1(750,860)
  Bottom Layer w7.87: v1(-250,840) 710,840 730,860 v1(750,860) ; v1(-250,1490) 187.84,1490 v1(220,1522.16)
FLASH: CN2.36 CN3.5 | length 2197.8
  Top Layer w7.87: CN2.36 745.28,804.72 v1(750,800)
  Bottom Layer w7.87: CN3.5 -525,1475 -340,1290 -340,1190.31 -339.68,1190 -339.68,791.85 -317.84,770 220,770 250,800 v1(750,800)
GND: C1.1 C2.1 C3.1 C4.1 CN1.5 CN1.19 CN1.27 CN2.3 CN2.4 CN2.7 CN2.8 CN2.11 CN2.12 CN2.16 CN2.21 CN2.22 CN2.37 CN2.38 CN2.41 CN2.42 CN3.8 CN4.1 CN5.2 CN5.8 CN5.15 CN5.17 CN5.30 LD1.2 R3.1 R4.2 R7.2 T1.2 U1.2 U1.EP | length 1611.8
  Top Layer w7.87: CN5.8 v1(-147.64,265) ; v1(-88.58,2009.76) CN1.27 ; CN5.15 v1(-9.85,275) -7.28,277.56 C4.1 ; v1(-9.84,2009.76) CN1.19 ; CN5.17 30,225.9 v1(30,185) ; v1(127.95,2009.76) CN1.5 ; CN5.30 v1(285.43,265)
  Top Layer w11.81: CN5.2 -263.78,228.34 -263.78,271.96 v1(-257.28,278.46) C3.1
  Top Layer w15.75: LD1.2 v1(-700,400) ; v3(-650,875) R3.1 ; R7.2 v3(-600,250) ; C1.1 -507.28,1057.72 v3(-525,1040) U1.EP ; U1.2 U1.EP ; R4.2 -452.72,767.72 -472.4,787.4 T1.2 -506.69,826.69 -507.28,827.28 C2.1 -507.28,902.28 -525,920 U1.EP ; v2(515,1435) 515.35,1434.65 CN2.3 ; v2(515.35,765.35) CN2.37 ; v2@515.35,1277.17 CN2.11 ; v2@515.35,1355.91 CN2.7 ; v2@525.55,1080 CN2.21@585,1080 ; CN2.38 v2@734.65,765.35 ; CN2.22 v2@734.65,1080.31 ; CN2.16 v2@734.65,1198.43 ; CN2.12 v2@734.65,1277.17 ; CN2.8 v2@734.65,1355.91 ; CN2.4 v2@734.65,1434.65
  other v2: 735,765 520,1080 735,1079.96 735,1198.07 735,1276.81 515,1277.52 735,1355.55 515,1356.26 735,1434.29
  other v3: -507.28,840
I2C_SCL: CN1.32 CN2.13 CN4.4 CN5.3 TP5.1 | length 3921.3
  Top Layer w7.87: v1(-550,600) -510,600 -500,610 -454.01,610 -300,764.01 v1(-300,1210) -300,1540 -220,1620 -220,1900 -310,1990 -310,2175 -209.33,2275.67 -140.67,2275.67 -127.95,2262.95 CN1.32 ; CN4.4 TP5.1 -500,125 -425.75,50.75 -274.25,50.75 -246.07,78.93 CN5.3 ; v1(510,1220) 527.8,1237.8 CN2.13
  Bottom Layer w7.87: v1(-550,600) -550,475 CN4.4 ; v1(-300,1210) 500,1210 v1(510,1220)
I2C_SDA: CN1.34 CN2.14 CN4.3 CN5.4 TP4.1 | length 4130
  Top Layer w7.87: CN5.4 -226.38,73.62 -265,35 -445,35 -575,165 TP4.1 -575,381.79 -551.77,405.02 -551.77,473.23 CN4.3 -500,570 -480,590 -450,590 -280,760 v1(-280,1190) -280,1530 -200,1610 -200,1910 -290,2000 -290,2170 -200.08,2259.92 -159.17,2259.92 -147.64,2248.39 CN1.34 ; CN2.14 737.2,1237.8 740,1235 v1(740,1236.48)
  Bottom Layer w7.87: v1(-280,1190) 670,1190 716.48,1236.48 v1(740,1236.48)
NetCN2_20: CN2.20 R1.1 | length 400.9
  Top Layer w7.87: R1.1 v1(500,1100) ; CN2.20 v1(730.31,1119.69)
  Bottom Layer w7.87: v1(500,1100) 519.69,1119.69 v1(730.31,1119.69)
NetLD1_1: LD1.1 R5.1 T1.3 | length 470.7
  Top Layer w7.87: LD1.1 -804.53,420.47 -792.72,432.28 R5.1 -792.72,607.28 -650,750 T1.3
NetLD2_2: LD2.2 R6.1 | length 77.8
  Top Layer w7.87: LD2.2 R6.1
NetLD3_2: LD3.2 R7.1 | length 77.8
  Top Layer w7.87: LD3.2 R7.1
NetR2_1: R2.1 R3.2 U1.5 | length 104.1
  Top Layer w7.87: -650,955 R2.1 -647.72,980 -615,980 -610,975 U1.5
NetR4_1: R4.1 SB1.2 T1.1 | length 191.1
  Top Layer w7.87: T1.1 -466.73,712.6 -447.05,732.28 R4.1 -377.95,732.28 SB1.2 R4.1@-425,729.33
PULLDOWN_LED2: CN2.15 CN5.9 R6.2 | length 2626.6
  Top Layer w7.87: R6.2 -625,325 v1(-600,350) -650,400 -650,575 -575,650 v1(-450,650) ; v1(-450,350) -425,325 -226.58,325 -188.29,286.71 -141.51,286.71 -127.95,273.15 CN5.9 ; v1(300,650) 300,1170 328.43,1198.43 CN2.15
  Bottom Layer w7.87: v1(-600,350) v1(-450,350) ; v1(-450,650) v1(300,650)
PWR_EN_LED1: CN1.25 CN2.19 CN3.7 CN4.17 CN5.6 SB1.1 | length 4468.3
  Top Layer w7.87: SB1.1 -375,790 -365,800 v1(-320,800) ; CN5.6 -187.01,117.01 -140,70 v1(180,70) ; CN1.25 -68.9,1980.53 20,1891.63 v1(20,1570) 20,1330 v1(200,1150) v1(200,800) CN4.17 ; v1(500,1130) 510.31,1119.69 CN2.19
  Bottom Layer w7.87: CN3.7 -725,1675 -620,1570 v1(20,1570) ; v1(-320,800) v1(200,800) ; v1(180,70) 200,90 200,275 150,325 150,475 CN4.17 ; v1(200,1150) 480,1150 v1(500,1130)
RESET#: CN1.21 CN2.17 CN4.18 CN5.5 | length 3059.9
  Top Layer w7.87: CN5.5 -206.7,106.7 -150,50 v1(195,50) ; CN1.21 -29.53,1992.06 60,1902.54 60,1330 v1(220,1170) 220,605 250,575 250,475 CN4.18 ; v1(500,1160) 500.94,1159.06 CN2.17
  Bottom Layer w7.87: v1(195,50) 215.75,70.75 215.75,284.25 200,300 CN4.18 ; v1(220,1170) 490,1170 v1(500,1160)
SHUTTER: CN1.23 CN2.35 CN3.6 CN5.7 | length 4585.8
  Top Layer w7.87: v1(-360.87,1250) -360.87,1539.13 v1(-350,1550) ; CN5.7@-165.35,224.4 CN5.7 -167.33,137.33 -125,95 220,95 282.52,32.48 409.27,32.48 460,83.21 v1(460,780) 482.84,780 507.56,804.72 CN2.35 ; CN1.23 -49.21,1989.48 40,1900.26 v1(40,1550)
  Bottom Layer w7.87: CN3.6 -665,1575 -640,1550 v1(-350,1550) v1(40,1550) ; v1(-360.87,1250) -360.87,790.76 -320.11,750 230,750 260,780 v1(460,780)
SPI_CLK: CN1.13 CN3.1 CN5.29 | length 3550.7
  Top Layer w7.87: CN3.1 -695,1075 -376.61,1393.39 v1(-376.61,1640) ; CN1.13 49.21,2000.79 120,1930 v1(120,1640) ; CN5.29 265.74,290.74 300,325 300,575 294.68,580.31 291.85,580.31 270,602.16 v1(270,670)
  Bottom Layer w7.87: CN3.1 -495,1075 -450,1030 -450,775.46 -344.54,670 v1(270,670) ; v1(-376.61,1640) v1(120,1640)
SPI_CS: CN1.11 CN3.3 CN5.19 | length 4227.9
  Top Layer w7.87: CN3.3 -715,1275 -450,1540 v1(-450,1660) ; CN5.19 68.89,167.38 105.96,130.31 234.68,130.31 301.03,63.97 396.22,63.97 420,87.75 420,640 v1(330,730) ; CN1.11 68.9,2006.1 140,1935 v1(140,1660)
  Bottom Layer w7.87: CN3.3 -615,1275 -400,1060 -400,770 -340,710 269.65,710 289.65,730 v1(330,730) ; v1(-450,1660) v1(140,1660)
SPI_MISO: CN1.15 CN3.4 CN5.18 | length 4351
  Top Layer w7.87: CN3.4 -715,1375 v1(-470,1620) ; CN1.15 29.53,1995.47 100,1925 v1(100,1620) ; CN5.18 49.68,225.91 49.68,164.31 99.43,114.57 225.43,114.57 291.77,48.23 402.75,48.23 440,85.48 440,660 v1(350,750)
  Bottom Layer w7.87: CN3.4 -475,1375 -380.55,1280.55 -380.55,780.55 -330,730 250,730 270,750 v1(350,750) ; v1(-470,1620) v1(100,1620)
SPI_MOSI: CN1.17 CN3.2 CN5.28 | length 3474.8
  Top Layer w7.87: CN3.2 -705,1175 -430,1450 v1(-430,1600) ; CN1.17 9.84,1980.53 80,1910.37 v1(80,1600) ; CN5.28 246.06,321.06 275,350 275,574.89 250,599.89 v1(250,690)
  Bottom Layer w7.87: CN3.2 -552.73,1175 -424.25,1046.52 -424.25,771.98 -342.27,690 v1(250,690) ; v1(-430,1600) v1(80,1600)
VCAM: CN4.2 JP1.2 | length 539.9
  Bottom Layer w15.75: JP1.2 -720,825 -680,785 -680,445 -660,425 CN4.2
pads on no net: CN1.0 CN1.1 CN1.3 CN1.6 CN1.7 CN1.8 CN1.9 CN1.37 CN1.38 CN2.5 CN2.6 CN2.9 CN2.10 CN2.18 CN2.34 CN5.31 CN5.32 H1.1 H2.1 H3.1 H4.1 H5.1 H6.1 U1.3

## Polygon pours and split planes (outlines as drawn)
GND on GND (split plane): 846.05,2314.51 846.05,47.69 818.45,20.1 -818.45,20.1 -846.04,47.69 -846.04,2314.51 -818.45,2342.11 818.45,2342.11
3V3 on VCC (split plane): 846.05,2314.51 846.05,47.69 818.45,20.1 -818.45,20.1 -846.04,47.69 -846.04,2314.51 -818.45,2342.11 818.45,2342.11

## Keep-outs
Keep-Out Layer:
  lines w3.94: 400,2275 400,2324.43 516.35,2324.43 516.35,2275 400,2275

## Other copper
Top Layer:
  text "1" at 414.41,2289.91 h20
  text ".Layer_Name" at -2295.66,-799.37 h118.11
  text ".GTL" at -654.13,-799.37 h118.11
Bottom Layer:
  text "4" at 488.98,2289.57 h20
  text ".GBL" at -1095.21,-800.63 h118.11
  text ".Layer_Name" at 531.33,-800.63 h118.11
GND (plane layer: these items are gaps in the copper):
  text "2" at 435,2290 h20
  text ".Layer_Name" at -2205,-800 h118.11
  text ".GP1" at -655,-800 h118.11
VCC (plane layer: these items are gaps in the copper):
  text "3" at 465,2290 h20
  text ".Layer_Name" at -2170,-800 h118.11
  text ".GP2" at -655,-800 h118.11

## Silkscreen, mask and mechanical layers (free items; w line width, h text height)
Top Overlay:
  lines w5: -600,572.44 -600,590 -400,590 ; -500,572.44 -500,590 ; -400,572.44 -400,590 ; -270,1020 -270,1000 ; -200,1000 -200,1020 ; -120,1020 -120,1000 -270,1000 ; -400,590 -330,590 -330,940 -270,1000
  text "OPENMV" at -275,2275 h80
  text "MB1683" at 370,2110 h80
  text "CAMERA MODULE BUNDLE" at 370,2060 h40
  text "J" at -680,2040 h600
  text "FOR MB1379" at 32.54,1930 h80
  text "G" at -475,1800 h400
  text "GND" at -710,1750 h80
  text "EN/LED1" at -710,1650 h80
  text "F" at -375,1625 h300
  text "1V8" at 710,1560 h80
  text "SHUTTER" at -710,1550 h80
  text "H" at -350,1500 h300
  text "FLASH" at -710,1450 h80
  text "MISO" at -710,1350 h80
  text "HREF" at -110,1280 h80 r90
  text "CS" at -710,1250 h80
  text "GND" at -240,1210 h80 r90
  text "SDA" at -170,1210 h80 r90
  text "MOSI" at -710,1150 h80
  text "2V8" at -450,1120 h80
  text "CLK" at -710,1050 h80
  text "3V3" at -240,1020 h80 r90
  text "SCL" at -170,1020 h80 r90
  text "VSYNC" at -110,1020 h80 r90
  text "C" at -50,1000 h300
  text "3V3" at -450,850 h80
  text "XCLK" at -260,770 h80 r90
  text "D6" at -180,770 h80 r90
  text "D4" at -80,770 h80 r90
  text "D2" at 20,770 h80 r90
  text "D0" at 130,770 h80 r90
  text "PWDN" at 220,770 h80 r90
  text "PCLK" at -260,580 h80 r90
  text "D7" at -180,580 h80 r90
  text "D5" at -80,580 h80 r90
  text "D3" at 20,580 h80 r90
  text "D1" at 130,580 h80 r90
  text "RES" at 220,580 h80 r90
  text "WAVESHARE" at 25,340 h40
  text "E" at 275,300 h300
  text "SCL" at -460,270 h80
  text "SDA" at -620,210 h80
  text "5V" at -500,90 h80
  text "I" at 425,50 h300
  text ".Layer_Name" at -2295.66,-799.37 h118.11
  text ".GTO" at -654.13,-799.37 h118.11
Bottom Overlay:
  text ".GBO" at -1095.21,-800.63 h118.11
  text ".Layer_Name" at 531.33,-800.63 h118.11
Top Paste:
  text ".Layer_Name" at -2295.66,-799.37 h118.11
  text ".GTP" at -654.13,-799.37 h118.11
Bottom Paste:
  text ".GBP" at -1095.21,-800.63 h118.11
  text ".Layer_Name" at 531.33,-800.63 h118.11
Top Solder:
  text ".Layer_Name" at -2295.66,-799.37 h118.11
  text ".GTS" at -654.13,-799.37 h118.11
Bottom Solder:
  text ".GBS" at -1095.21,-800.63 h118.11
  text ".Layer_Name" at 531.33,-800.63 h118.11
M1-Board Shape:
  the board outline again, w5
M2-Board Dimensions:
  text ".Layer_Name" at -2295.66,-799.37 h118.11
  text ".GM2" at -654.13,-799.37 h118.11
M5-Top Constraints:
  lines w5: 231.08,706.96 231.08,628.22 ; 231.08,628.22 506.67,352.63 821.63,352.63 861,392 861,1888.06 861,2084.91 841.32,2104.6 -261.05,2104.6 -280.73,2084.91 -280.73,1277.83 -245.3,1242.39 65.73,1242.39 cw(c65.73,1077.04) 231.08,1077.04 231.08,628.22 ; -675.59,364.96 -675.59,1770.51 281.1,1770.51 281.1,364.96 -675.59,364.96 ; -319.92,1610 310,1610 310,2239.92 -319.92,2239.92 -319.92,1610 ; -79.94,1706.96 266.51,1706.96 266.51,2053.42 -79.94,2053.42 -79.94,1706.96
  text "MB1379" at -248.92,2117.63 h35
M14-Top Assembly:
  text ".Layer_Name" at -2295.66,-799.37 h118.11
  text ".GM14" at -654.13,-799.37 h118.11
M15-Bottom Assembly:
  text ".GM15" at -1095.21,-800.63 h118.11
  text ".Layer_Name" at 531.33,-800.63 h118.11
Drill Drawing:
  drawing of 486 lines, arcs and shapes, not listed
  text "PCB SPECIFICATIONS :" at -3080.63,4209.53 h118.11
  text "PCB : TYPE 3" at 2726.13,4202.74 h118.11
  text "A.   MATERIAL :" at -3080.63,4052.05 h118.11
  text "FR-4" at -1564.88,4052.05 h118.11
  text "TG-170" at -915.28,4052.05 h118.11
  text "X  TG-150" at -196.77,4052.05 h118.11
  text "TG-140" at 433.15,4052.05 h118.11
  text "ASPECT-RATIO, AXE Z :" at 2726.13,3986.21 h118.11
  text "B.   MATERIAL FAMILY :" at -3080.63,3933.94 h118.11
  text "N/A" at -1564.88,3933.94 h118.11
  text "WHITE" at -780.3,3817.86 h118.11
  text "C.   SOLDERMASK COLOR :" at -3080.63,3815.83 h118.11
  text "GREEN" at -1564.88,3815.83 h118.11
  text "X  BLUE" at -196.77,3815.83 h118.11
  text "BLACK" at 433.15,3815.83 h118.11
  text "6:1 to 8:1 / LEVEL \"B\"" at 2726.86,3720.56 h118.11
  text "D.   SILKSCREEN COLOR :" at -3080.63,3697.72 h118.11
  text "X  WHITE" at -1564.88,3697.72 h118.11
  text "YELLOW" at -915.28,3697.72 h118.11
  text "BLACK" at -196.77,3697.72 h118.11
  text "Blue ink PANTONE 2955" at 433.15,3697.72 h118.11
  text "E.   SURFACE FINISH :" at -3080.63,3579.61 h118.11
  text "X  ENIG" at -1564.88,3579.61 h118.11
  text "IMMERSION SILVER" at -915.28,3579.61 h118.11
  text "IMMERSION TIN" at 433.15,3579.61 h118.11
  text "MINIMUM PARAMETERS" at 2727.93,3500.05 h118.11
  text "HASL" at -1564.88,3461.5 h118.11
  text "HASL (PB-FREE)" at -915.28,3461.5 h118.11
  text "GOLDEN FINGER" at 433.15,3461.5 h118.11
  text "F.   IMPEDANCE CONTROL :" at -3080.63,3343.39 h118.11
  text "X  NO" at -1564.88,3343.39 h118.11
  text "YES  (SEE IMPEDANCE TABLE FOR DETAIL INFORMATION)" at -915.28,3343.39 h118.11
  text "DEFAULT" at 2727.93,3283.51 h118.11
  text "G.   THROUGH VIA :" at -3080.63,3225.28 h118.11
  text "PLUG THE VIAS WHICH ARE COVERED WITH SOLDERMASK ONE OR TWO SIDE." at -1564.88,3225.28 h118.11
  text "PLUG MATERIAL :" at -1564.88,3107.17 h118.11
  text "X  SOLDERMASK" at -560.94,3107.17 h118.11
  text "NON-CONDUCTIVE EPOXY." at 433.15,3107.17 h118.11
  text "TRACKS : 0.127mm           / GAPS : 0.127mm" at 2727.93,3057.13 h118.11
  text "H.   STACK-UP :" at -3080.63,2989.06 h118.11
  text "SEE LAYER STACK-UP SEQUENCE FOR OVERALL THICKNESS." at -1564.88,2989.06 h118.11
  text "Symbol" at 1302.5,2542.5 h72
  text "Count" at 1808.38,2542.5 h72
  text "Hole Size" at 2398.22,2542.5 h72
  text "Plated" at 3547.88,2542.5 h72
  text "Hole Type" at 4053.76,2542.5 h72
  text "Drill Layer Pair" at 4787.56,2542.5 h72
  text "Via/Pad" at 6287.11,2542.5 h72
  text "Pad Shape" at 6876.96,2542.5 h72
  text "Template" at 7622.76,2542.5 h72
  text "109" at 1808.38,2392.5 h60
  text "7.87mil (0.200mm)" at 2398.22,2392.5 h60
  text "PTH" at 3547.88,2392.5 h60
  text "Round" at 4053.76,2392.5 h60
  text "Top Layer - Bottom Layer" at 4787.56,2392.5 h60
  text "Via" at 6287.11,2392.5 h60
  text "Rounded" at 6876.96,2392.5 h60
  text "v40h20m0mx0" at 7622.76,2392.5 h60
  text "8" at 1808.38,2242.5 h60
  text "11.81mil (0.300mm)" at 2398.22,2242.5 h60
  text "PTH" at 3547.88,2242.5 h60
  text "Round" at 4053.76,2242.5 h60
  text "Top Layer - Bottom Layer" at 4787.56,2242.5 h60
  text "Via" at 6287.11,2242.5 h60
  text "Rounded" at 6876.96,2242.5 h60
  text "v60h30m0mx0" at 7622.76,2242.5 h60
  text "13" at 1808.38,2092.5 h60
  text "15.75mil (0.400mm)" at 2398.22,2092.5 h60
  text "PTH" at 3547.88,2092.5 h60
  text "Round" at 4053.76,2092.5 h60
  text "Top Layer - Bottom Layer" at 4787.56,2092.5 h60
  text "Via" at 6287.11,2092.5 h60
  text "Rounded" at 6876.96,2092.5 h60
  text "v60h40m0mx0" at 7622.76,2092.5 h60
  text "2" at 1808.38,1942.5 h60
  text "23.62mil (0.600mm)" at 2398.22,1942.5 h60
  text "NPTH" at 3547.88,1942.5 h60
  text "Round" at 4053.76,1942.5 h60
  text "Top Layer - Bottom Layer" at 4787.56,1942.5 h60
  text "Pad" at 6287.11,1942.5 h60
  text "Rounded" at 6876.96,1942.5 h60
  text "c0hn60m65" at 7622.76,1942.5 h60
  text "8" at 1808.38,1792.5 h60
  text "39.37mil (1.000mm)" at 2398.22,1792.5 h60
  text "PTH" at 3547.88,1792.5 h60
  text "Round" at 4053.76,1792.5 h60
  text "Top Layer - Bottom Layer" at 4787.56,1792.5 h60
  text "Pad" at 6287.11,1792.5 h60
  text "Rounded" at 6876.96,1792.5 h60
  text "(Mixed)" at 7622.76,1792.5 h60
  text "3" at 1808.38,1642.5 h60
  text "41.34mil (1.050mm)" at 2398.22,1642.5 h60
  text "PTH" at 3547.88,1642.5 h60
  text "Round" at 4053.76,1642.5 h60
  text "Top Layer - Bottom Layer" at 4787.56,1642.5 h60
  text "Pad" at 6287.11,1642.5 h60
  text "(Mixed)" at 6876.96,1642.5 h60
  text "(Mixed)" at 7622.76,1642.5 h60
  text "18" at 1808.38,1492.5 h60
  text "43.31mil (1.100mm)" at 2398.22,1492.5 h60
  text "PTH" at 3547.88,1492.5 h60
  text "Round" at 4053.76,1492.5 h60
  text "Top Layer - Bottom Layer" at 4787.56,1492.5 h60
  text "Pad" at 6287.11,1492.5 h60
  text "Rounded" at 6876.96,1492.5 h60
  text "(Mixed)" at 7622.76,1492.5 h60
  text "2" at 1808.38,1342.5 h60
  text "125.98mil (3.200mm)" at 2398.22,1342.5 h60
  text "PTH" at 3547.88,1342.5 h60
  text "Round" at 4053.76,1342.5 h60
  text "Top Layer - Bottom Layer" at 4787.56,1342.5 h60
  text "Pad" at 6287.11,1342.5 h60
  text "Rounded" at 6876.96,1342.5 h60
  text "c600h320m610" at 7622.76,1342.5 h60
  text "6" at 1808.38,1192.5 h60
  text "137.80mil (3.500mm)" at 2398.22,1192.5 h60
  text "NPTH" at 3547.88,1192.5 h60
  text "Round" at 4053.76,1192.5 h60
  text "Top Layer - Bottom Layer" at 4787.56,1192.5 h60
  text "Pad" at 6287.11,1192.5 h60
  text "Rounded" at 6876.96,1192.5 h60
  text "c0hn350m355" at 7622.76,1192.5 h60
  text "169 Total" at 1808.38,1042.5 h60
  text "Layer" at 1257.5,662.5 h60
  text "Name" at 1667.41,662.5 h60
  text "Material" at 2597.16,662.5 h60
  text "Thickness" at 3456.92,662.5 h60
  text "Constant" at 4106.76,662.5 h60
  text "Board Layer Stack" at 4676.62,662.5 h60
  text "1" at 1257.5,542.5 h60
  text "Top Overlay" at 1667.41,542.5 h60
  text "2" at 1257.5,422.5 h60
  text "Top Solder" at 1667.41,422.5 h60
  text "Solder Resist" at 2597.16,422.5 h60
  text "0.59mil" at 3456.92,422.5 h60
  text "3.5" at 4106.76,422.5 h60
  text "3" at 1257.5,302.5 h60
  text "Top Layer" at 1667.41,302.5 h60
  text "Copper" at 2597.16,302.5 h60
  text "1.38mil" at 3456.92,302.5 h60
  text "4" at 1257.5,182.5 h60
  text "Dielectric 1" at 1667.41,182.5 h60
  text "FR-4" at 2597.16,182.5 h60
  text "20.00mil" at 3456.92,182.5 h60
  text "4.2" at 4106.76,182.5 h60
  text "5" at 1257.5,62.5 h60
  text "GND" at 1667.41,62.5 h60
  text "Copper" at 2597.16,62.5 h60
  text "1.42mil" at 3456.92,62.5 h60
  text "6" at 1257.5,-57.5 h60
  text "Dielectric 3" at 1667.41,-57.5 h60
  text "16.00mil" at 3456.92,-57.5 h60
  text "4.2" at 4106.76,-57.5 h60
  text "7" at 1257.5,-177.5 h60
  text "VCC" at 1667.41,-177.5 h60
  text "Copper" at 2597.16,-177.5 h60
  text "1.42mil" at 3456.92,-177.5 h60
  text "8" at 1257.5,-297.5 h60
  text "Dielectric 2" at 1667.41,-297.5 h60
  text "20.00mil" at 3456.92,-297.5 h60
  text "4.2" at 4106.76,-297.5 h60
  text "9" at 1257.5,-417.5 h60
  text "Bottom Layer" at 1667.41,-417.5 h60
  text "Copper" at 2597.16,-417.5 h60
  text "1.38mil" at 3456.92,-417.5 h60
  text "10" at 1257.5,-537.5 h60
  text "Bottom Solder" at 1667.41,-537.5 h60
  text "Solder Resist" at 2597.16,-537.5 h60
  text "0.59mil" at 3456.92,-537.5 h60
  text "3.5" at 4106.76,-537.5 h60
  text "11" at 1257.5,-657.5 h60
  text "Bottom Overlay" at 1667.41,-657.5 h60
  text ".Layer_Name" at -2295.66,-799.37 h118.11
  text ".DRL" at -654.13,-799.37 h118.11
M20-Top Title Box:
  circle w10: c775.37,-1063.96 r51.18
  region: 756.68,-779.07 145.37,-779.07 118.04,-848.96 70.37,-897.19 15.37,-823.96 15.37,-758.96 60.37,-703.96 116.9,-689.07 756.68,-689.07
  region: 205.37,-1107 -218.1,-1107 -178.99,-1008.86 130.37,-1008.86 148.04,-978.96 234.99,-1079.29
  lines w10: -178.99,-1008.86 167.15,-1008.86 46.43,-869.57 cw(c117.45,-793.04) 126.9,-689.07 786.9,-689.07 756.9,-779.07 ; -48.53,-679.34 cw(c46.99,-717.54) 56.3,-615.09 ; -46.99,-678.06 -218.1,-1107 542.64,-1107 ccw(c552.42,-999.35) 652.79,-1039.49 ; 21.51,-832.97 234.99,-1079.29 ; 31.51,-832.97 240.37,-1073.96 ; 31.51,-822.97 240.37,-1063.96 ; 35.37,-779.07 546.9,-779.07 ; 36.51,-817.97 245.37,-1058.96 ; 41.51,-812.97 250.37,-1053.96 ; 46.51,-807.97 255.37,-1048.96 ; 51.51,-802.97 260.37,-1043.96 ; 53.67,-726.1 262.52,-967.09 ; 56.35,-615.1 822.09,-615.1 652.83,-1039.4 ; 56.51,-797.97 263.22,-1036.49 ; 56.51,-787.97 265.37,-1028.96 ; 56.51,-777.97 265.37,-1018.96 ; 56.51,-742.97 265.37,-983.96 ; 61.51,-772.97 270.37,-1013.96 ; 61.51,-757.97 270.37,-998.96 ; 115.52,-1009.39 ccw(c119.65,-988.31) 131.37,-970.32 ; 158.29,-778.54 ccw(c157.27,-800.88) 144.27,-819.07 237.37,-926.5 cw(c166.35,-1003.03) 195.2,-1103.37 ; 405.58,-1098.96 519.34,-769.07 ; 414.34,-1097 527.3,-769.41 ; 419.34,-1097 532.3,-769.41 ; 429.34,-1097 542.3,-769.41 ; 439.34,-1097 552.3,-769.41 ; 449.34,-1097 562.3,-769.41 ; 459.34,-1097 572.3,-769.41 ; 469.34,-1097 582.3,-769.41 ; 479.34,-1097 592.3,-769.41 ; 489.34,-1097 602.3,-769.41 ; 497.55,-1098.96 611.31,-769.07 ; 611.31,-779.07 756.68,-779.07 ; 730.37,-778.96 760.37,-688.96 ; 736.9,-779.07 766.9,-689.07 ; 746.9,-779.07 776.9,-689.07
  lines w11.81: -2650,-1260 893.31,-1260 893.31,-472.6 -2650,-472.6 ; -2650,-1063.15 -287.8,-1063.15 ; -2650,-866.3 -287.8,-866.3 ; -2650,-669.45 -287.8,-669.45 ; -2649.98,-1260 -2649.98,-472.6 ; -1075.2,-1260 -1075.2,-669.45 ; -287.8,-1260 -287.8,-472.6 ; 405.58,-1098.96 497.55,-1098.96
  text "Project: '.Board_Name'" at -2610.62,-599.21 h118.11
  text "Layer:" at -2610.61,-799.37 h118.11
  text "Gerber:" at -1036.26,-799.37 h118.11
  text "Variant: '.VariantName'" at -2610.62,-996.22 h118.11
  text "Ref: '.Board_Reference'" at -1031.26,-996.22 h118.11
  text "R" at 755.37,-1093.96 h60
  text "Date: '.Board_Document_Date'" at -2610.62,-1193.07 h118.11
  text "Rev: '.Board_PCB_Revision'" at -1033.5,-1193.07 h118.11
M21-Bottom Title Box:
  circle w10: c-2524.69,-1063.96 r51.18
  region: -1954.69,-1107 -1531.22,-1107 -1570.33,-1008.86 -1879.69,-1008.86 -1897.36,-978.96 -1984.31,-1079.29
  region: -2506,-779.07 -1894.69,-779.07 -1867.36,-848.96 -1819.69,-897.19 -1764.69,-823.96 -1764.69,-758.96 -1809.69,-703.96 -1866.22,-689.07 -2506,-689.07
  lines w10: -2526.23,-689.07 -2496.23,-779.07 ; -2516.23,-689.07 -2486.23,-779.07 ; -2509.69,-688.96 -2479.69,-778.96 ; -2506.23,-779.07 -2536.23,-689.07 -1876.22,-689.07 cw(c-1866.77,-793.04) -1795.76,-869.57 -1916.47,-1008.86 -1570.33,-1008.86 ; -2506,-779.07 -2360.63,-779.07 ; -2402.15,-1039.4 -2571.41,-615.1 -1805.68,-615.1 ; -2402.11,-1039.49 ccw(c-2301.75,-999.35) -2291.96,-1107 -1531.22,-1107 -1702.34,-678.06 ; -2360.63,-769.07 -2246.87,-1098.96 ; -2351.62,-769.41 -2238.66,-1097 ; -2341.62,-769.41 -2228.66,-1097 ; -2331.62,-769.41 -2218.66,-1097 ; -2321.62,-769.41 -2208.66,-1097 ; -2311.62,-769.41 -2198.66,-1097 ; -2301.62,-769.41 -2188.66,-1097 ; -2296.22,-779.07 -1784.69,-779.07 ; -2291.62,-769.41 -2178.66,-1097 ; -2281.62,-769.41 -2168.66,-1097 ; -2276.62,-769.41 -2163.66,-1097 ; -2268.66,-769.07 -2154.91,-1098.96 ; -2019.69,-1013.96 -1810.83,-772.97 ; -2019.69,-998.96 -1810.83,-757.97 ; -2014.69,-1028.96 -1805.83,-787.97 ; -2014.69,-1018.96 -1805.83,-777.97 ; -2014.69,-983.96 -1805.83,-742.97 ; -2012.55,-1036.49 -1805.83,-797.97 ; -2011.85,-967.09 -1802.99,-726.1 ; -2009.69,-1043.96 -1800.83,-802.97 ; -2004.69,-1048.96 -1795.83,-807.97 ; -1999.69,-1053.96 -1790.83,-812.97 ; -1994.69,-1058.96 -1785.83,-817.97 ; -1989.69,-1073.96 -1780.83,-832.97 ; -1989.69,-1063.96 -1780.83,-822.97 ; -1984.31,-1079.29 -1770.83,-832.97 ; -1944.52,-1103.37 cw(c-1915.68,-1003.03) -1986.69,-926.5 -1893.59,-819.07 ccw(c-1906.59,-800.88) -1907.61,-778.54 ; -1880.69,-970.32 ccw(c-1868.97,-988.31) -1864.84,-1009.39 ; -1805.63,-615.09 cw(c-1796.31,-717.54) -1700.8,-679.34
  lines w11.81: -2246.87,-1098.96 -2154.91,-1098.96 ; -1468.9,-1260 -1468.9,-472.6 ; -1468.9,-1063.15 893.31,-1063.15 ; -1468.9,-866.3 893.31,-866.3 ; -1468.9,-669.45 893.31,-669.45 ; -681.5,-1260 -681.5,-669.45 ; -2650,-1260 893.31,-1260 893.31,-472.6 -2650,-472.6 -2650,-1260
  text "Project: '.Board_Name'" at 846.3,-599.21 h118.11
  text "Gerber:" at -728.06,-799.37 h118.11
  text "Layer:" at 846.29,-799.37 h118.11
  text "Ref: '.Board_Reference'" at -728.06,-996.22 h118.11
  text "Variant: '.VariantName'" at 846.3,-996.22 h118.11
  text "R" at -2504.69,-1093.96 h60
  text "Rev: '.Board_PCB_Revision'" at -725.82,-1193.07 h118.11
  text "Date: '.Board_Document_Date'" at 846.3,-1193.07 h118.11

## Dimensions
-866.14,2322.83 to 866.14,2322.83 on M2-Board Dimensions
-748.03,2244.09 to 748.03,2244.09 on M2-Board Dimensions
-600,1950 to 600,1950 on M2-Board Dimensions
-748.03,2244.09 to -748.03,118.11 on M2-Board Dimensions
-826.77,2362.2 to -826.77,0 on M2-Board Dimensions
